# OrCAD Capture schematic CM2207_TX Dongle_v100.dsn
size Custom; title: CM2207_TX  Dongle_Reference_Schematic; rev: 1.00; company: C-MEDIA ELECTRONICS Inc.; note: Main; note: 6F., 100, Sec. 4, Civil Boulevard, Taipei, Taiwan, R.O.C.
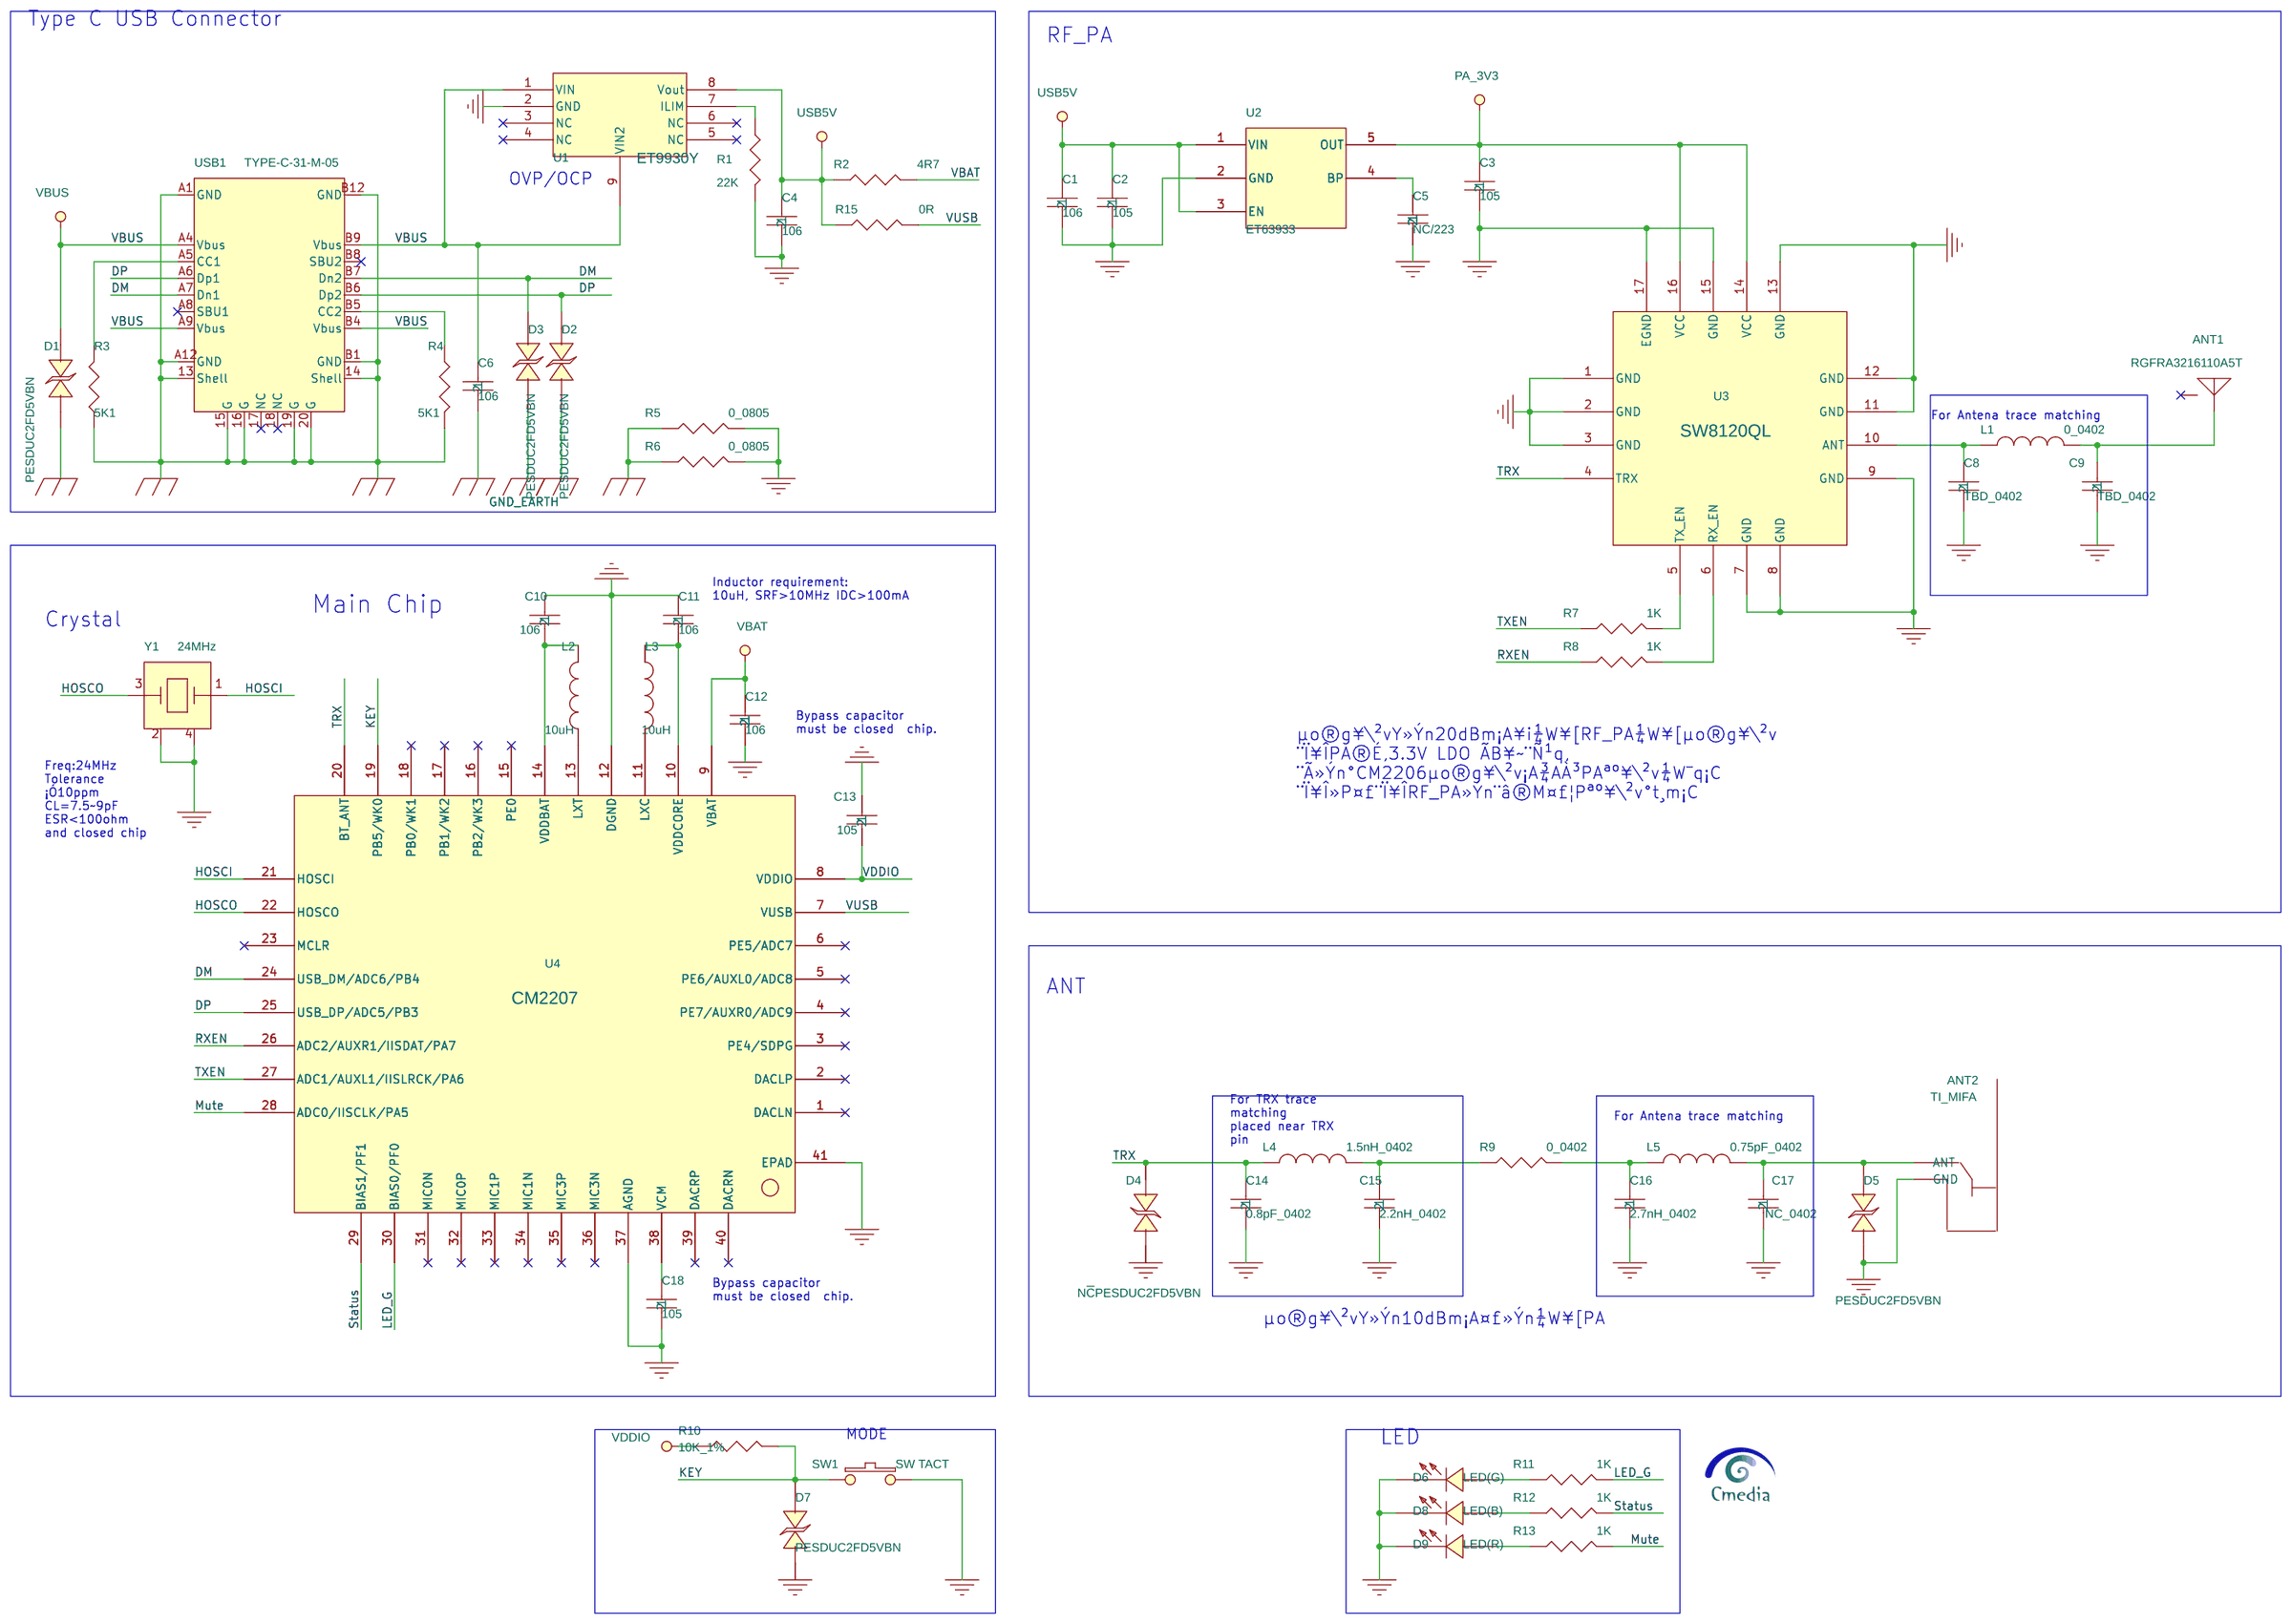
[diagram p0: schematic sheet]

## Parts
ANT1  RGFRA3216110A5T  [ANT3216120A5T]
ANT2  TI_MIFA  [TI_MIFA]
C1  106  [C0603]
C2  105  [C0603]
C3  105  [C0603]
C4  106  [C0603]
C5  NC/223  [C0603]
C6  106  [C0603]
C8  TBD_0402  [C0402]
C9  TBD_0402  [C0402]
C10  106  [C0603]
C11  106  [C0603]
C12  106  [C0603]
C13  105  [C0603]
C14  0.8pF_0402  [C0402]
C15  2.2nH_0402  [C0402]
C16  2.7nH_0402  [C0402]
C17  NC_0402  [C0402]
C18  105  [C0603]
D1  PESDUC2FD5VBN  [D0402]
D2  PESDUC2FD5VBN  [D0402]
D3  PESDUC2FD5VBN  [D0402]
D4  NC\PESDUC2FD5VBN  [D0402]
D5  PESDUC2FD5VBN  [D0402]
D6  LED(G)  [D0603]
D7  PESDUC2FD5VBN  [D0402]
D8  LED(B)  [D0603]
D9  LED(R)  [D0603]
L1  0_0402  [L0402]
L2  10uH  [L0603]
L3  10uH  [L0603]
L4  1.5nH_0402  [L0402]
L5  0.75pF_0402  [L0402]
R1  22K  [R0603]
R2  4R7  [R0603]
R3  5K1  [R0603]
R4  5K1  [R0603]
R5  0_0805  [R0805]
R6  0_0805  [R0805]
R7  1K  [R0603]
R8  1K  [R0603]
R9  0_0402  [R0402]
R10  10K_1%  [R0603]
R11  1K  [R0603]
R12  1K  [R0603]
R13  1K  [R0603]
R15  0R  [R0603]
SW1  SW TACT  [STSW-39X29]
U1  ET9930Y  [DFN8(2*2)]
U2  ET63933  [SOT23-5]
U3  SW8120QL  [QFN-3X3-16]
U4  CM2207  [QFN-40_6X4]
USB1  TYPE-C-31-M-05  [TUSB31CF-073-L-SMD]
Y1  24MHz  [SOSC-3.2X2]

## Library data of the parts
ANT1 = ANTENNA_0: Classification: ³³²¡¤Ñ½u; Part Number: D0-RFANT3216120A5T; Pin Type: SMD; Size: ANT_3216
ANT2 = ANTENNA_1
C1 = CAP_NP_12
C2 = CAP_NP_3
C3 = CAP_NP_4
C4 = CAP_NP_15
C5 = CAP_NP_14
C6 = CAP_NP_10
C8 = CAP_NP_7
C9 = CAP_NP_1
C10 = CAP_NP
C11 = CAP_NP_6
C12 = CAP_NP_16
C13 = CAP_NP_9
C14 = CAP_NP_11
C15 = CAP_NP_2
C16 = CAP_NP_5
C17 = CAP_NP_13
C18 = CAP_NP_8
D1-D5 D7 = DIODE_TVS_BI-DIR
D6 D8 D9 = LED
L1-L5 = INDUCTOR
R1-R13 R15 = R
SW1 = SW_TACT-SPST_SM
U1 = CMI120_48
U2 = ZTA_2
U3 = CMI120_47
U4 = CMI120_49
USB1 = HEADER_4_4: 1ST PART FIELD: USB Micro B-Type SMD
Y1 = CRYSTAL_SM_0

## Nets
DGND: ANT2.2(GND) C1.2 C2.2 C3.2 C4.2 C5.2 C8.2 C9.2 C10.1 C11.1 C12.2 C13.1 C14.2 C15.2 C16.2 C17.2 C18.2 D4.1 D5.1 D6.2(CATHODE) D7.1 D8.2(CATHODE) D9.2(CATHODE) R1.1 R5.1 R6.1 SW1.2 U1.2(GND) U2.2(GND) U3.1(GND) U3.2(GND) U3.3(GND) U3.7(GND) U3.8(GND) U3.9(GND) U3.11(GND) U3.12(GND) U3.13(GND) U3.15(GND) U3.17(EGND) U4.12(DGND) U4.37(AGND) U4.41(EPAD) Y1.2 Y1.4
GND_EARTH: C6.2 D1.1 D2.1 D3.1 R3.1 R4.1 R5.2 R6.2 USB1.13(Shell) USB1.14(Shell) USB1.15(G) USB1.16(G) USB1.19(G) USB1.20(G) USB1.A1(GND) USB1.A12(GND) USB1.B1(GND) USB1.B12(GND)
VBAT: C12.1 R2.1 U4.9(VBAT)
VBUS: C6.1 D1.2 U1.1(VIN) U1.9(VIN2) USB1.A4(Vbus) USB1.A9(Vbus) USB1.B4(Vbus) USB1.B9(Vbus)
VDDIO: C13.2 R10.1 U4.8(VDDIO)
DM: D3.2 U4.24(USB_DM/ADC6/PB4) USB1.A7(Dn1) USB1.B7(Dn2)
DP: D2.2 U4.25(USB_DP/ADC5/PB3) USB1.A6(Dp1) USB1.B6(Dp2)
HOSCI: U4.21(HOSCI) Y1.1
HOSCO: U4.22(HOSCO) Y1.3
KEY: D7.2 R10.2 SW1.1 U4.19(PB5/WK0)
LED_G: R11.2 U4.30(BIAS0/PF0)
Mute: R13.2 U4.28(ADC0/IISCLK/PA5)
PA_3V3: C3.1 U2.5(OUT) U3.14(VCC) U3.16(VCC)
RXEN: R8.2 U4.26(ADC2/AUXR1/IISDAT/PA7)
Status: R12.2 U4.29(BIAS1/PF1)
TRX: C14.1 D4.2 L4.1 U3.4(TRX) U4.20(BT_ANT)
TXEN: R7.2 U4.27(ADC1/AUXL1/IISLRCK/PA6)
USB5V: C1.1 C2.1 C4.1 R2.2 R15.2 U1.8(Vout) U2.1(VIN) U2.3(EN)
VUSB: R15.1 U4.7(VUSB)
N27873642: C10.2 L2.2 U4.14(VDDBAT)
N27873646: C11.2 L3.2 U4.10(VDDCORE)
N27897130: D6.1(ANODE) R11.1
N27897342: D8.1(ANODE) R12.1
N27897505: D9.1(ANODE) R13.1
N27942191: C18.1 U4.38(VCM)
N27943463: R3.2 USB1.A5(CC1)
N27943489: R4.2 USB1.B5(CC2)
N27945465: C5.1 U2.4(BP)
N27945595: ANT1.1 C9.1 L1.2
N27945607: C8.1 L1.1 U3.10(ANT)
N27945650: R7.1 U3.5(TX_EN)
N27945652: R8.1 U3.6(RX_EN)
N27946667: C15.1 L4.2 R9.2
N27946673: C16.1 L5.1 R9.1
N27946679: ANT2.1(ANT) C17.1 D5.2 L5.2
N27954834: R1.2 U1.7(ILIM)
N27957918: L3.1 U4.11(LXC)
N27957919: L2.1 U4.13(LXT)

Not connected (* = marked no-connect by the designer): ANT1 2*; U1 3(NC)* 4(NC)* 5(NC)* 6(NC)*; U4 1(DACLN)* 2(DACLP)* 3(PE4/SDPG)* 4(PE7/AUXR0/ADC9)* 5(PE6/AUXL0/ADC8)* 6(PE5/ADC7)* 15(PE0)* 16(PB2/WK3)* 17(PB1/WK2)* 18(PB0/WK1)* 23(MCLR)* 31(MIC0N)* 32(MIC0P)* 33(MIC1P)* 34(MIC1N)* 35(MIC3P)* 36(MIC3N)* 39(DACRP)* 40(DACRN)*; USB1 17(NC)* 18(NC)* A8(SBU1)* B8(SBU2)*

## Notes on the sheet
- Type C USB Connector
- RF_PA
- OVP/OCP
- For Antena trace matching
- Inductor requirement:
  10uH, SRF>10MHz IDC>100mA
- Main Chip
- Crystal
- Bypass capacitor
  must be closed  chip.
- µo®g¥\²v­Y»Ý­n20dBm¡A¥i¼W¥[RF_PA¼W¥[µo®g¥\²v
  ¨Ï¥ÎPA®É,3.3V LDO ÃB¥~¨Ñ¹q,
  ¨Ã»Ý­n­°CM2206µo®g¥\²v¡A¾AÀ³PAªº¥\²v¼W¯q¡C
  ¨Ï¥Î»P¤£¨Ï¥ÎRF_PA»Ý­n¨â®M¤£¦Pªº¥\²v°t¸m¡C
- Freq:24MHz
  Tolerance
  ¡Ó10ppm
  CL=7.5~9pF
  ESR<100ohm
  and closed chip
- ANT
- For TRX trace
  matching
  placed near TRX
  pin
- For Antena trace matching
- Bypass capacitor
  must be closed  chip.
- µo®g¥\²v­Y»Ý­n10dBm¡A¤£»Ý­n¼W¥[PA
- MODE
- LED
